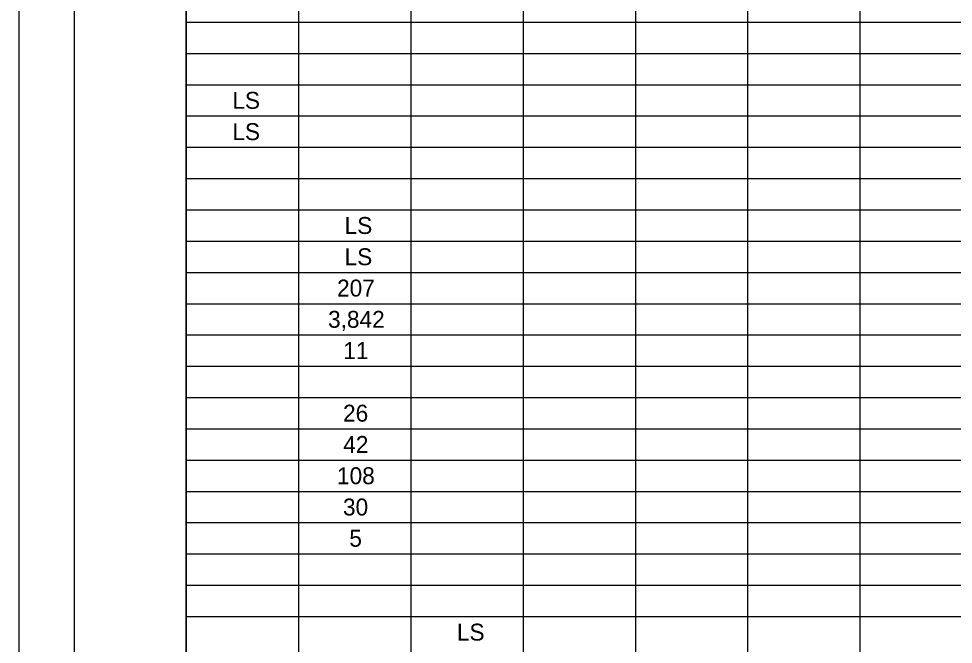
# Model space of a CAD drawing. Extents: x 0 to 34, y 0 to 22.
# Drawn here: x 0 to 8.36, y 10.89 to 16.49 of the extents above; entities that cross this region are included whole.
import ezdxf

# ---------------------------------------------------------------- set-up
doc = ezdxf.new("R2010")
doc.units = 0
for name, color, linetype in [('SH_Border', 7, 'Continuous'), ('SH_Cut_Line', 7, 'Continuous'), ('SH_Text', 7, 'Continuous')]:
    doc.layers.add(name, color=color, linetype=linetype)

msp = doc.modelspace()

# ---------------------------------------------------------------- linework, layer by layer
at = {"layer": 'SH_Border'}
for points in [[(0.5, 21.5), (1.5, 21.5), (1.5, 0.5), (0.5, 0.5)], [(1.5, 21.5), (33.5, 21.5), (33.5, 0.5), (1.5, 0.5)]]:
    msp.add_lwpolyline(points, close=True, dxfattribs=at)
at = {"layer": 'SH_Cut_Line'}
msp.add_lwpolyline([(0, 0), (34, 0), (34, 22), (0, 22)], close=True, dxfattribs=at)
at = {"layer": 'SH_Text'}
for p, q in [((1.5, 21.5), (1.5, 0.5024)), ((2.5046, 20.9401), (2.5046, 0.5024)), ((3.5092, 20.9401), (3.5092, 0.5024)), ((4.5138, 20.9401), (4.5138, 0.5024)), ((5.5184, 20.9401), (5.5184, 0.5024)), ((6.5229, 20.9401), (6.5229, 0.5024)), ((7.5275, 20.9401), (7.5275, 0.5024)), ((1.5, 16.4606), (32, 16.4606)), ((1.5, 16.1806), (32, 16.1806)), ((1.5, 15.9006), (32, 15.9006)), ((1.5, 15.6207), (32, 15.6207)), ((1.5, 15.3407), (32, 15.3407)), ((1.5, 15.0607), (32, 15.0607)), ((1.5, 14.7808), (32, 14.7808)), ((1.5, 14.5008), (32, 14.5008)), ((1.5, 14.2208), (32, 14.2208)), ((1.5, 13.9409), (32, 13.9409)), ((1.5, 13.6609), (32, 13.6609)), ((1.5, 13.3809), (32, 13.3809)), ((1.5, 13.101), (32, 13.101)), ((1.5, 12.821), (32, 12.821)), ((1.5, 12.541), (32, 12.541)), ((1.5, 12.2611), (32, 12.2611)), ((1.5, 11.9811), (32, 11.9811)), ((1.5, 11.7011), (32, 11.7011)), ((1.5, 11.4212), (32, 11.4212)), ((1.5, 11.1412), (32, 11.1412))]:
    msp.add_line(p, q, dxfattribs=at)

# ---------------------------------------------------------------- texts
for s, height, p in [('LS', 0.15151, (1.9117, 15.6849)), ('LS', 0.15151, (1.9117, 15.4049)), ('LS', 0.15151, (2.9163, 14.565)), ('LS', 0.15151, (2.9163, 14.2851)), ('207', 0.15151, (2.8486, 14.0051)), ('3,842', 0.15151, (2.7683, 13.7251)), ('11', 0.15151, (2.9039, 13.4452)), ('26', 0.15151, (2.9023, 12.8852)), ('42', 0.15151, (2.904, 12.6053)), ('108', 0.15151, (2.8481, 12.3253)), ('30', 0.15151, (2.9018, 12.0453)), ('5', 0.1515, (2.9587, 11.7654)), ('LS', 0.15151, (3.9209, 10.9255))]:
    msp.add_text(s, height=height, dxfattribs=at).set_placement(p)

doc.saveas('drawing.dxf')
